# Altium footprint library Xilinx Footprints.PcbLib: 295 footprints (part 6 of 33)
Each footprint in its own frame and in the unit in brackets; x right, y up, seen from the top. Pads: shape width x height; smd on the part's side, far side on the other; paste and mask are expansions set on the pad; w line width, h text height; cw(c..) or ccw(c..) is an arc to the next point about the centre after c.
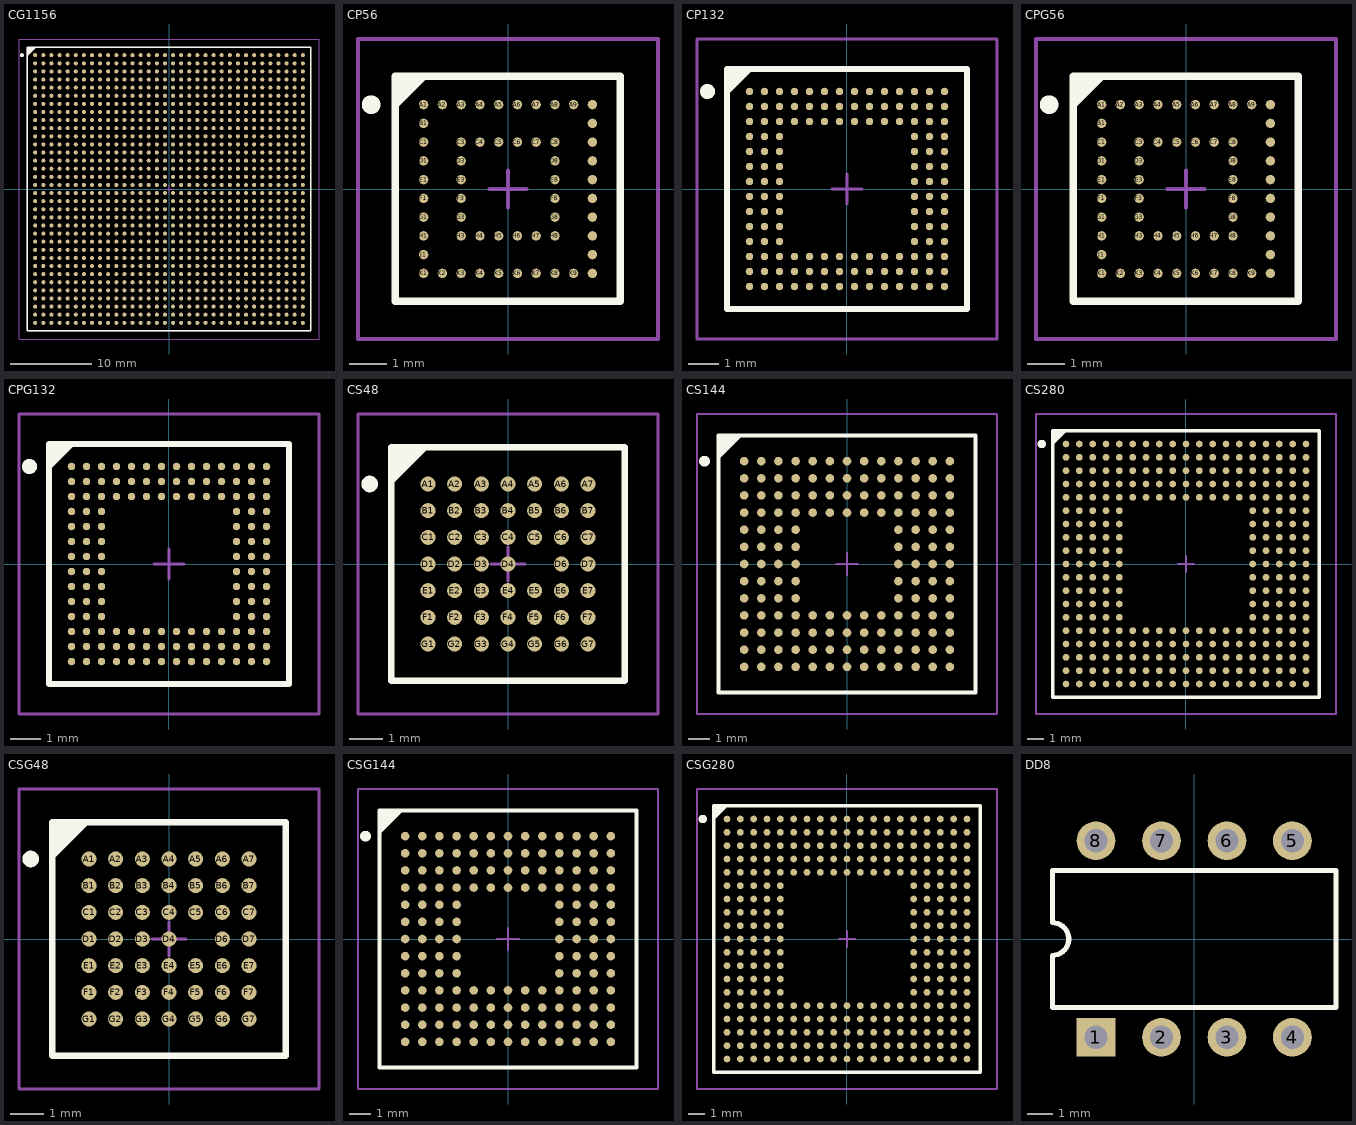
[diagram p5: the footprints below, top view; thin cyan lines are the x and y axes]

## CG1156 [mm] "1156-Ball Ceramic Ball Grid Array (CG1156)"
height 3.11
pads (1156):
  round 0.5 smd: A1(-16.5,16.5) A2(-15.5,16.5) A3(-14.5,16.5) A4(-13.5,16.5) A5(-12.5,16.5) A6(-11.5,16.5) A7(-10.5,16.5) A8(-9.5,16.5) A9(-8.5,16.5) A10(-7.5,16.5) A11(-6.5,16.5) A12(-5.5,16.5) A13(-4.5,16.5) A14(-3.5,16.5) A15(-2.5,16.5) A16(-1.5,16.5) A17(-0.5,16.5) A18(0.5,16.5) A19(1.5,16.5) A20(2.5,16.5) A21(3.5,16.5) A22(4.5,16.5) A23(5.5,16.5) A24(6.5,16.5) A25(7.5,16.5) A26(8.5,16.5) A27(9.5,16.5) A28(10.5,16.5) A29(11.5,16.5) A30(12.5,16.5) A31(13.5,16.5) A32(14.5,16.5) A33(15.5,16.5) A34(16.5,16.5) AA1(-16.5,-3.5) AA2(-15.5,-3.5) AA3(-14.5,-3.5) AA4(-13.5,-3.5) AA5(-12.5,-3.5) AA6(-11.5,-3.5) AA7(-10.5,-3.5) AA8(-9.5,-3.5) AA9(-8.5,-3.5) AA10(-7.5,-3.5) AA11(-6.5,-3.5) AA12(-5.5,-3.5) AA13(-4.5,-3.5) AA14(-3.5,-3.5) AA15(-2.5,-3.5) AA16(-1.5,-3.5) AA17(-0.5,-3.5) AA18(0.5,-3.5) AA19(1.5,-3.5) AA20(2.5,-3.5) AA21(3.5,-3.5) AA22(4.5,-3.5) AA23(5.5,-3.5) AA24(6.5,-3.5) AA25(7.5,-3.5) AA26(8.5,-3.5) AA27(9.5,-3.5) AA28(10.5,-3.5) AA29(11.5,-3.5) AA30(12.5,-3.5) AA31(13.5,-3.5) AA32(14.5,-3.5) AA33(15.5,-3.5) AA34(16.5,-3.5) AB1(-16.5,-4.5) AB2(-15.5,-4.5) AB3(-14.5,-4.5) AB4(-13.5,-4.5) AB5(-12.5,-4.5) AB6(-11.5,-4.5) AB7(-10.5,-4.5) AB8(-9.5,-4.5) AB9(-8.5,-4.5) AB10(-7.5,-4.5) AB11(-6.5,-4.5) AB12(-5.5,-4.5) AB13(-4.5,-4.5) AB14(-3.5,-4.5) AB15(-2.5,-4.5) AB16(-1.5,-4.5) AB17(-0.5,-4.5) AB18(0.5,-4.5) AB19(1.5,-4.5) AB20(2.5,-4.5) AB21(3.5,-4.5) AB22(4.5,-4.5) AB23(5.5,-4.5) AB24(6.5,-4.5) AB25(7.5,-4.5) AB26(8.5,-4.5) AB27(9.5,-4.5) AB28(10.5,-4.5) AB29(11.5,-4.5) AB30(12.5,-4.5) AB31(13.5,-4.5) AB32(14.5,-4.5) AB33(15.5,-4.5) AB34(16.5,-4.5) AC1(-16.5,-5.5) AC2(-15.5,-5.5) AC3(-14.5,-5.5) AC4(-13.5,-5.5) AC5(-12.5,-5.5) AC6(-11.5,-5.5) AC7(-10.5,-5.5) AC8(-9.5,-5.5) AC9(-8.5,-5.5) AC10(-7.5,-5.5) AC11(-6.5,-5.5) AC12(-5.5,-5.5) AC13(-4.5,-5.5) AC14(-3.5,-5.5) AC15(-2.5,-5.5) AC16(-1.5,-5.5) AC17(-0.5,-5.5) AC18(0.5,-5.5) AC19(1.5,-5.5) AC20(2.5,-5.5) AC21(3.5,-5.5) AC22(4.5,-5.5) AC23(5.5,-5.5) AC24(6.5,-5.5) AC25(7.5,-5.5) AC26(8.5,-5.5) AC27(9.5,-5.5) AC28(10.5,-5.5) AC29(11.5,-5.5) AC30(12.5,-5.5) AC31(13.5,-5.5) AC32(14.5,-5.5) AC33(15.5,-5.5) AC34(16.5,-5.5) AD1(-16.5,-6.5) AD2(-15.5,-6.5) AD3(-14.5,-6.5) AD4(-13.5,-6.5) AD5(-12.5,-6.5) AD6(-11.5,-6.5) AD7(-10.5,-6.5) AD8(-9.5,-6.5) AD9(-8.5,-6.5) AD10(-7.5,-6.5) AD11(-6.5,-6.5) AD12(-5.5,-6.5) AD13(-4.5,-6.5) AD14(-3.5,-6.5) AD15(-2.5,-6.5) AD16(-1.5,-6.5) AD17(-0.5,-6.5) AD18(0.5,-6.5) AD19(1.5,-6.5) AD20(2.5,-6.5) AD21(3.5,-6.5) AD22(4.5,-6.5) AD23(5.5,-6.5) AD24(6.5,-6.5) AD25(7.5,-6.5) AD26(8.5,-6.5) AD27(9.5,-6.5) AD28(10.5,-6.5) AD29(11.5,-6.5) AD30(12.5,-6.5) AD31(13.5,-6.5) AD32(14.5,-6.5) AD33(15.5,-6.5) AD34(16.5,-6.5) AE1(-16.5,-7.5) AE2(-15.5,-7.5) AE3(-14.5,-7.5) AE4(-13.5,-7.5) AE5(-12.5,-7.5) AE6(-11.5,-7.5) AE7(-10.5,-7.5) AE8(-9.5,-7.5) AE9(-8.5,-7.5) AE10(-7.5,-7.5) AE11(-6.5,-7.5) AE12(-5.5,-7.5) AE13(-4.5,-7.5) AE14(-3.5,-7.5) AE15(-2.5,-7.5) AE16(-1.5,-7.5) AE17(-0.5,-7.5) AE18(0.5,-7.5) AE19(1.5,-7.5) AE20(2.5,-7.5) AE21(3.5,-7.5) AE22(4.5,-7.5) AE23(5.5,-7.5) AE24(6.5,-7.5) AE25(7.5,-7.5) AE26(8.5,-7.5) AE27(9.5,-7.5) AE28(10.5,-7.5) AE29(11.5,-7.5) AE30(12.5,-7.5) AE31(13.5,-7.5) AE32(14.5,-7.5) AE33(15.5,-7.5) AE34(16.5,-7.5) AF1(-16.5,-8.5) AF2(-15.5,-8.5) AF3(-14.5,-8.5) AF4(-13.5,-8.5) AF5(-12.5,-8.5) AF6(-11.5,-8.5) AF7(-10.5,-8.5) AF8(-9.5,-8.5) AF9(-8.5,-8.5) AF10(-7.5,-8.5) AF11(-6.5,-8.5) AF12(-5.5,-8.5) AF13(-4.5,-8.5) AF14(-3.5,-8.5) AF15(-2.5,-8.5) AF16(-1.5,-8.5) AF17(-0.5,-8.5) AF18(0.5,-8.5) AF19(1.5,-8.5) AF20(2.5,-8.5) AF21(3.5,-8.5) AF22(4.5,-8.5) AF23(5.5,-8.5) AF24(6.5,-8.5) AF25(7.5,-8.5) AF26(8.5,-8.5) AF27(9.5,-8.5) AF28(10.5,-8.5) AF29(11.5,-8.5) AF30(12.5,-8.5) AF31(13.5,-8.5) AF32(14.5,-8.5) AF33(15.5,-8.5) AF34(16.5,-8.5) AG1(-16.5,-9.5) AG2(-15.5,-9.5) AG3(-14.5,-9.5) AG4(-13.5,-9.5) AG5(-12.5,-9.5) AG6(-11.5,-9.5) AG7(-10.5,-9.5) AG8(-9.5,-9.5) AG9(-8.5,-9.5) AG10(-7.5,-9.5) AG11(-6.5,-9.5) AG12(-5.5,-9.5) AG13(-4.5,-9.5) AG14(-3.5,-9.5) AG15(-2.5,-9.5) AG16(-1.5,-9.5) AG17(-0.5,-9.5) AG18(0.5,-9.5) AG19(1.5,-9.5) AG20(2.5,-9.5) AG21(3.5,-9.5) AG22(4.5,-9.5) AG23(5.5,-9.5) AG24(6.5,-9.5) AG25(7.5,-9.5) AG26(8.5,-9.5) AG27(9.5,-9.5) AG28(10.5,-9.5) AG29(11.5,-9.5) AG30(12.5,-9.5) AG31(13.5,-9.5) AG32(14.5,-9.5) AG33(15.5,-9.5) AG34(16.5,-9.5) AH1(-16.5,-10.5) AH2(-15.5,-10.5) AH3(-14.5,-10.5) AH4(-13.5,-10.5) AH5(-12.5,-10.5) AH6(-11.5,-10.5) AH7(-10.5,-10.5) AH8(-9.5,-10.5) AH9(-8.5,-10.5) AH10(-7.5,-10.5) AH11(-6.5,-10.5) AH12(-5.5,-10.5) AH13(-4.5,-10.5) AH14(-3.5,-10.5) AH15(-2.5,-10.5) AH16(-1.5,-10.5) AH17(-0.5,-10.5) AH18(0.5,-10.5) AH19(1.5,-10.5) AH20(2.5,-10.5) AH21(3.5,-10.5) AH22(4.5,-10.5) AH23(5.5,-10.5) AH24(6.5,-10.5) AH25(7.5,-10.5) AH26(8.5,-10.5) AH27(9.5,-10.5) AH28(10.5,-10.5) AH29(11.5,-10.5) AH30(12.5,-10.5) AH31(13.5,-10.5) AH32(14.5,-10.5) AH33(15.5,-10.5) AH34(16.5,-10.5) AJ1(-16.5,-11.5) AJ2(-15.5,-11.5) AJ3(-14.5,-11.5) AJ4(-13.5,-11.5) AJ5(-12.5,-11.5) AJ6(-11.5,-11.5) AJ7(-10.5,-11.5) AJ8(-9.5,-11.5) AJ9(-8.5,-11.5) AJ10(-7.5,-11.5) AJ11(-6.5,-11.5) AJ12(-5.5,-11.5) AJ13(-4.5,-11.5) AJ14(-3.5,-11.5) AJ15(-2.5,-11.5) AJ16(-1.5,-11.5) AJ17(-0.5,-11.5) AJ18(0.5,-11.5) AJ19(1.5,-11.5) AJ20(2.5,-11.5) AJ21(3.5,-11.5) AJ22(4.5,-11.5) AJ23(5.5,-11.5) AJ24(6.5,-11.5) AJ25(7.5,-11.5) AJ26(8.5,-11.5) AJ27(9.5,-11.5) AJ28(10.5,-11.5) AJ29(11.5,-11.5) AJ30(12.5,-11.5) AJ31(13.5,-11.5) AJ32(14.5,-11.5) AJ33(15.5,-11.5) AJ34(16.5,-11.5) AK1(-16.5,-12.5) AK2(-15.5,-12.5) AK3(-14.5,-12.5) AK4(-13.5,-12.5) AK5(-12.5,-12.5) AK6(-11.5,-12.5) AK7(-10.5,-12.5) AK8(-9.5,-12.5) AK9(-8.5,-12.5) AK10(-7.5,-12.5) AK11(-6.5,-12.5) AK12(-5.5,-12.5) AK13(-4.5,-12.5) AK14(-3.5,-12.5) AK15(-2.5,-12.5) AK16(-1.5,-12.5) AK17(-0.5,-12.5) AK18(0.5,-12.5) AK19(1.5,-12.5) AK20(2.5,-12.5) AK21(3.5,-12.5) AK22(4.5,-12.5) AK23(5.5,-12.5) AK24(6.5,-12.5) AK25(7.5,-12.5) AK26(8.5,-12.5) AK27(9.5,-12.5) AK28(10.5,-12.5) AK29(11.5,-12.5) AK30(12.5,-12.5) AK31(13.5,-12.5) AK32(14.5,-12.5) AK33(15.5,-12.5) AK34(16.5,-12.5) AL1(-16.5,-13.5) AL2(-15.5,-13.5) AL3(-14.5,-13.5) AL4(-13.5,-13.5) AL5(-12.5,-13.5) AL6(-11.5,-13.5) AL7(-10.5,-13.5) AL8(-9.5,-13.5) AL9(-8.5,-13.5) AL10(-7.5,-13.5) AL11(-6.5,-13.5) AL12(-5.5,-13.5) AL13(-4.5,-13.5) AL14(-3.5,-13.5) AL15(-2.5,-13.5) AL16(-1.5,-13.5) AL17(-0.5,-13.5) AL18(0.5,-13.5) AL19(1.5,-13.5) AL20(2.5,-13.5) AL21(3.5,-13.5) AL22(4.5,-13.5) AL23(5.5,-13.5) AL24(6.5,-13.5) AL25(7.5,-13.5) AL26(8.5,-13.5) AL27(9.5,-13.5) AL28(10.5,-13.5) AL29(11.5,-13.5) AL30(12.5,-13.5) AL31(13.5,-13.5) AL32(14.5,-13.5) AL33(15.5,-13.5) AL34(16.5,-13.5) AM1(-16.5,-14.5) AM2(-15.5,-14.5) AM3(-14.5,-14.5) AM4(-13.5,-14.5) AM5(-12.5,-14.5) AM6(-11.5,-14.5) AM7(-10.5,-14.5) AM8(-9.5,-14.5) AM9(-8.5,-14.5) AM10(-7.5,-14.5) AM11(-6.5,-14.5) AM12(-5.5,-14.5) AM13(-4.5,-14.5) AM14(-3.5,-14.5) AM15(-2.5,-14.5) AM16(-1.5,-14.5) AM17(-0.5,-14.5) AM18(0.5,-14.5) AM19(1.5,-14.5) AM20(2.5,-14.5) AM21(3.5,-14.5) AM22(4.5,-14.5) AM23(5.5,-14.5) AM24(6.5,-14.5) AM25(7.5,-14.5) AM26(8.5,-14.5) AM27(9.5,-14.5) AM28(10.5,-14.5) AM29(11.5,-14.5) AM30(12.5,-14.5) AM31(13.5,-14.5) AM32(14.5,-14.5) AM33(15.5,-14.5) AM34(16.5,-14.5) AN1(-16.5,-15.5) AN2(-15.5,-15.5) AN3(-14.5,-15.5) AN4(-13.5,-15.5) AN5(-12.5,-15.5) AN6(-11.5,-15.5) AN7(-10.5,-15.5) AN8(-9.5,-15.5) AN9(-8.5,-15.5) AN10(-7.5,-15.5) AN11(-6.5,-15.5) AN12(-5.5,-15.5) AN13(-4.5,-15.5) AN14(-3.5,-15.5) AN15(-2.5,-15.5) AN16(-1.5,-15.5) AN17(-0.5,-15.5) AN18(0.5,-15.5) AN19(1.5,-15.5) AN20(2.5,-15.5) AN21(3.5,-15.5) AN22(4.5,-15.5) AN23(5.5,-15.5) AN24(6.5,-15.5) AN25(7.5,-15.5) AN26(8.5,-15.5) AN27(9.5,-15.5) AN28(10.5,-15.5) AN29(11.5,-15.5) AN30(12.5,-15.5) AN31(13.5,-15.5) AN32(14.5,-15.5) AN33(15.5,-15.5) AN34(16.5,-15.5) AP1(-16.5,-16.5) AP2(-15.5,-16.5) AP3(-14.5,-16.5) AP4(-13.5,-16.5) AP5(-12.5,-16.5) AP6(-11.5,-16.5) AP7(-10.5,-16.5) AP8(-9.5,-16.5) AP9(-8.5,-16.5) AP10(-7.5,-16.5) AP11(-6.5,-16.5) AP12(-5.5,-16.5) AP13(-4.5,-16.5) AP14(-3.5,-16.5) AP15(-2.5,-16.5) AP16(-1.5,-16.5) AP17(-0.5,-16.5) AP18(0.5,-16.5) AP19(1.5,-16.5) AP20(2.5,-16.5) AP21(3.5,-16.5) AP22(4.5,-16.5) AP23(5.5,-16.5) AP24(6.5,-16.5) AP25(7.5,-16.5) AP26(8.5,-16.5) AP27(9.5,-16.5) AP28(10.5,-16.5) AP29(11.5,-16.5) AP30(12.5,-16.5) AP31(13.5,-16.5) AP32(14.5,-16.5) AP33(15.5,-16.5) AP34(16.5,-16.5) B1(-16.5,15.5) B2(-15.5,15.5) B3(-14.5,15.5) B4(-13.5,15.5) B5(-12.5,15.5) B6(-11.5,15.5) B7(-10.5,15.5) B8(-9.5,15.5) B9(-8.5,15.5) B10(-7.5,15.5) B11(-6.5,15.5) B12(-5.5,15.5) B13(-4.5,15.5) B14(-3.5,15.5) B15(-2.5,15.5) B16(-1.5,15.5) B17(-0.5,15.5) B18(0.5,15.5) B19(1.5,15.5) B20(2.5,15.5) B21(3.5,15.5) B22(4.5,15.5) B23(5.5,15.5) B24(6.5,15.5) B25(7.5,15.5) B26(8.5,15.5) B27(9.5,15.5) B28(10.5,15.5) B29(11.5,15.5) B30(12.5,15.5) B31(13.5,15.5) B32(14.5,15.5) B33(15.5,15.5) B34(16.5,15.5) C1(-16.5,14.5) C2(-15.5,14.5) C3(-14.5,14.5) C4(-13.5,14.5) C5(-12.5,14.5) C6(-11.5,14.5) C7(-10.5,14.5) C8(-9.5,14.5) C9(-8.5,14.5) C10(-7.5,14.5) C11(-6.5,14.5) C12(-5.5,14.5) C13(-4.5,14.5) C14(-3.5,14.5) C15(-2.5,14.5) C16(-1.5,14.5) C17(-0.5,14.5) C18(0.5,14.5) C19(1.5,14.5) C20(2.5,14.5) C21(3.5,14.5) C22(4.5,14.5) C23(5.5,14.5) C24(6.5,14.5) C25(7.5,14.5) C26(8.5,14.5) C27(9.5,14.5) C28(10.5,14.5) C29(11.5,14.5) C30(12.5,14.5) C31(13.5,14.5) C32(14.5,14.5) C33(15.5,14.5) C34(16.5,14.5) D1(-16.5,13.5) D2(-15.5,13.5) D3(-14.5,13.5) D4(-13.5,13.5) D5(-12.5,13.5) D6(-11.5,13.5) D7(-10.5,13.5) D8(-9.5,13.5) D9(-8.5,13.5) D10(-7.5,13.5) D11(-6.5,13.5) D12(-5.5,13.5) D13(-4.5,13.5) D14(-3.5,13.5) D15(-2.5,13.5) D16(-1.5,13.5) D17(-0.5,13.5) D18(0.5,13.5) D19(1.5,13.5) D20(2.5,13.5) D21(3.5,13.5) D22(4.5,13.5) D23(5.5,13.5) D24(6.5,13.5) D25(7.5,13.5) D26(8.5,13.5) D27(9.5,13.5) D28(10.5,13.5) D29(11.5,13.5) D30(12.5,13.5) D31(13.5,13.5) D32(14.5,13.5) D33(15.5,13.5) D34(16.5,13.5) E1(-16.5,12.5) E2(-15.5,12.5) E3(-14.5,12.5) E4(-13.5,12.5) E5(-12.5,12.5) E6(-11.5,12.5) E7(-10.5,12.5) E8(-9.5,12.5) E9(-8.5,12.5) E10(-7.5,12.5) E11(-6.5,12.5) E12(-5.5,12.5) E13(-4.5,12.5) E14(-3.5,12.5) E15(-2.5,12.5) E16(-1.5,12.5) E17(-0.5,12.5) E18(0.5,12.5) E19(1.5,12.5) E20(2.5,12.5) E21(3.5,12.5) E22(4.5,12.5) E23(5.5,12.5) E24(6.5,12.5) E25(7.5,12.5) E26(8.5,12.5) E27(9.5,12.5) E28(10.5,12.5) E29(11.5,12.5) E30(12.5,12.5) E31(13.5,12.5) E32(14.5,12.5) E33(15.5,12.5) E34(16.5,12.5) F1(-16.5,11.5) F2(-15.5,11.5) F3(-14.5,11.5) F4(-13.5,11.5) F5(-12.5,11.5) F6(-11.5,11.5) F7(-10.5,11.5) F8(-9.5,11.5) F9(-8.5,11.5) F10(-7.5,11.5) F11(-6.5,11.5) F12(-5.5,11.5) F13(-4.5,11.5) F14(-3.5,11.5) F15(-2.5,11.5) F16(-1.5,11.5) F17(-0.5,11.5) F18(0.5,11.5) F19(1.5,11.5) F20(2.5,11.5) F21(3.5,11.5) F22(4.5,11.5) F23(5.5,11.5) F24(6.5,11.5) F25(7.5,11.5) F26(8.5,11.5) F27(9.5,11.5) F28(10.5,11.5) F29(11.5,11.5) F30(12.5,11.5) F31(13.5,11.5) F32(14.5,11.5) F33(15.5,11.5) F34(16.5,11.5) G1(-16.5,10.5) G2(-15.5,10.5) G3(-14.5,10.5) G4(-13.5,10.5) G5(-12.5,10.5) G6(-11.5,10.5) G7(-10.5,10.5) G8(-9.5,10.5) G9(-8.5,10.5) G10(-7.5,10.5) G11(-6.5,10.5) G12(-5.5,10.5) G13(-4.5,10.5) G14(-3.5,10.5) G15(-2.5,10.5) G16(-1.5,10.5) G17(-0.5,10.5) G18(0.5,10.5) G19(1.5,10.5) G20(2.5,10.5) G21(3.5,10.5) G22(4.5,10.5) G23(5.5,10.5) G24(6.5,10.5) G25(7.5,10.5) G26(8.5,10.5) G27(9.5,10.5) G28(10.5,10.5) G29(11.5,10.5) G30(12.5,10.5) G31(13.5,10.5) G32(14.5,10.5) G33(15.5,10.5) G34(16.5,10.5) H1(-16.5,9.5) H2(-15.5,9.5) H3(-14.5,9.5) H4(-13.5,9.5) H5(-12.5,9.5) H6(-11.5,9.5) H7(-10.5,9.5) H8(-9.5,9.5) H9(-8.5,9.5) H10(-7.5,9.5) H11(-6.5,9.5) H12(-5.5,9.5) H13(-4.5,9.5) H14(-3.5,9.5) H15(-2.5,9.5) H16(-1.5,9.5) H17(-0.5,9.5) H18(0.5,9.5) H19(1.5,9.5) H20(2.5,9.5) H21(3.5,9.5) H22(4.5,9.5) H23(5.5,9.5) H24(6.5,9.5) H25(7.5,9.5) H26(8.5,9.5) H27(9.5,9.5) H28(10.5,9.5) H29(11.5,9.5) H30(12.5,9.5) H31(13.5,9.5) H32(14.5,9.5) H33(15.5,9.5) H34(16.5,9.5) J1(-16.5,8.5) J2(-15.5,8.5) J3(-14.5,8.5) J4(-13.5,8.5) J5(-12.5,8.5) J6(-11.5,8.5) J7(-10.5,8.5) J8(-9.5,8.5) J9(-8.5,8.5) J10(-7.5,8.5) J11(-6.5,8.5) J12(-5.5,8.5) J13(-4.5,8.5) J14(-3.5,8.5) J15(-2.5,8.5) J16(-1.5,8.5) J17(-0.5,8.5) J18(0.5,8.5) J19(1.5,8.5) J20(2.5,8.5) J21(3.5,8.5) J22(4.5,8.5) J23(5.5,8.5) J24(6.5,8.5) J25(7.5,8.5) J26(8.5,8.5) J27(9.5,8.5) J28(10.5,8.5) J29(11.5,8.5) J30(12.5,8.5) J31(13.5,8.5) J32(14.5,8.5) J33(15.5,8.5) J34(16.5,8.5) K1(-16.5,7.5) K2(-15.5,7.5) K3(-14.5,7.5) K4(-13.5,7.5) K5(-12.5,7.5) K6(-11.5,7.5) K7(-10.5,7.5) K8(-9.5,7.5) K9(-8.5,7.5) K10(-7.5,7.5) K11(-6.5,7.5) K12(-5.5,7.5) K13(-4.5,7.5) K14(-3.5,7.5) K15(-2.5,7.5) K16(-1.5,7.5) K17(-0.5,7.5) K18(0.5,7.5) K19(1.5,7.5) K20(2.5,7.5) K21(3.5,7.5) K22(4.5,7.5) K23(5.5,7.5) K24(6.5,7.5) K25(7.5,7.5) K26(8.5,7.5) K27(9.5,7.5) K28(10.5,7.5) K29(11.5,7.5) K30(12.5,7.5) K31(13.5,7.5) K32(14.5,7.5) K33(15.5,7.5) K34(16.5,7.5) L1(-16.5,6.5) L2(-15.5,6.5) L3(-14.5,6.5) L4(-13.5,6.5) L5(-12.5,6.5) L6(-11.5,6.5) L7(-10.5,6.5) L8(-9.5,6.5) L9(-8.5,6.5) L10(-7.5,6.5) L11(-6.5,6.5) L12(-5.5,6.5) L13(-4.5,6.5) L14(-3.5,6.5) L15(-2.5,6.5) L16(-1.5,6.5) L17(-0.5,6.5) L18(0.5,6.5) L19(1.5,6.5) L20(2.5,6.5) L21(3.5,6.5) L22(4.5,6.5) L23(5.5,6.5) L24(6.5,6.5) L25(7.5,6.5) L26(8.5,6.5) L27(9.5,6.5) L28(10.5,6.5) L29(11.5,6.5) L30(12.5,6.5) L31(13.5,6.5) L32(14.5,6.5) L33(15.5,6.5) L34(16.5,6.5) M1(-16.5,5.5) M2(-15.5,5.5) M3(-14.5,5.5) M4(-13.5,5.5) M5(-12.5,5.5) M6(-11.5,5.5) M7(-10.5,5.5) M8(-9.5,5.5) M9(-8.5,5.5) M10(-7.5,5.5) M11(-6.5,5.5) M12(-5.5,5.5) M13(-4.5,5.5) M14(-3.5,5.5) M15(-2.5,5.5) M16(-1.5,5.5) M17(-0.5,5.5) M18(0.5,5.5) M19(1.5,5.5) M20(2.5,5.5) M21(3.5,5.5) M22(4.5,5.5) M23(5.5,5.5) M24(6.5,5.5) M25(7.5,5.5) M26(8.5,5.5) M27(9.5,5.5) M28(10.5,5.5) M29(11.5,5.5) M30(12.5,5.5) M31(13.5,5.5) M32(14.5,5.5) M33(15.5,5.5) M34(16.5,5.5) N1(-16.5,4.5) N2(-15.5,4.5) N3(-14.5,4.5) N4(-13.5,4.5) N5(-12.5,4.5) N6(-11.5,4.5) N7(-10.5,4.5) N8(-9.5,4.5) N9(-8.5,4.5) N10(-7.5,4.5) N11(-6.5,4.5) N12(-5.5,4.5) N13(-4.5,4.5) N14(-3.5,4.5) N15(-2.5,4.5) N16(-1.5,4.5) N17(-0.5,4.5) N18(0.5,4.5) N19(1.5,4.5) N20(2.5,4.5) N21(3.5,4.5) N22(4.5,4.5) N23(5.5,4.5) N24(6.5,4.5) N25(7.5,4.5) N26(8.5,4.5) N27(9.5,4.5) N28(10.5,4.5) N29(11.5,4.5) N30(12.5,4.5) N31(13.5,4.5) N32(14.5,4.5) N33(15.5,4.5) N34(16.5,4.5) P1(-16.5,3.5) P2(-15.5,3.5) P3(-14.5,3.5) P4(-13.5,3.5) P5(-12.5,3.5) P6(-11.5,3.5) P7(-10.5,3.5) P8(-9.5,3.5) P9(-8.5,3.5) P10(-7.5,3.5) P11(-6.5,3.5) P12(-5.5,3.5) P13(-4.5,3.5) P14(-3.5,3.5) P15(-2.5,3.5) P16(-1.5,3.5) P17(-0.5,3.5) P18(0.5,3.5) P19(1.5,3.5) P20(2.5,3.5) P21(3.5,3.5) P22(4.5,3.5) P23(5.5,3.5) P24(6.5,3.5) P25(7.5,3.5) P26(8.5,3.5) P27(9.5,3.5) P28(10.5,3.5) P29(11.5,3.5) P30(12.5,3.5) P31(13.5,3.5) P32(14.5,3.5) P33(15.5,3.5) P34(16.5,3.5) R1(-16.5,2.5) R2(-15.5,2.5) R3(-14.5,2.5) R4(-13.5,2.5) R5(-12.5,2.5) R6(-11.5,2.5) R7(-10.5,2.5) R8(-9.5,2.5) R9(-8.5,2.5) R10(-7.5,2.5) R11(-6.5,2.5) R12(-5.5,2.5) R13(-4.5,2.5) R14(-3.5,2.5) R15(-2.5,2.5) R16(-1.5,2.5) R17(-0.5,2.5) R18(0.5,2.5) R19(1.5,2.5) R20(2.5,2.5) R21(3.5,2.5) R22(4.5,2.5) R23(5.5,2.5) R24(6.5,2.5) R25(7.5,2.5) R26(8.5,2.5) R27(9.5,2.5) R28(10.5,2.5) R29(11.5,2.5) R30(12.5,2.5) R31(13.5,2.5) R32(14.5,2.5) R33(15.5,2.5) R34(16.5,2.5) T1(-16.5,1.5) T2(-15.5,1.5) T3(-14.5,1.5) T4(-13.5,1.5) T5(-12.5,1.5) T6(-11.5,1.5) T7(-10.5,1.5) T8(-9.5,1.5) T9(-8.5,1.5) T10(-7.5,1.5) T11(-6.5,1.5) T12(-5.5,1.5) T13(-4.5,1.5) T14(-3.5,1.5) T15(-2.5,1.5) T16(-1.5,1.5) T17(-0.5,1.5) T18(0.5,1.5) T19(1.5,1.5) T20(2.5,1.5) T21(3.5,1.5) T22(4.5,1.5) T23(5.5,1.5) T24(6.5,1.5) T25(7.5,1.5) T26(8.5,1.5) T27(9.5,1.5) T28(10.5,1.5) T29(11.5,1.5) T30(12.5,1.5) T31(13.5,1.5) T32(14.5,1.5) T33(15.5,1.5) T34(16.5,1.5) U1(-16.5,0.5) U2(-15.5,0.5) U3(-14.5,0.5) U4(-13.5,0.5) U5(-12.5,0.5) U6(-11.5,0.5) U7(-10.5,0.5) U8(-9.5,0.5) U9(-8.5,0.5) U10(-7.5,0.5) U11(-6.5,0.5) U12(-5.5,0.5) U13(-4.5,0.5) U14(-3.5,0.5) U15(-2.5,0.5) U16(-1.5,0.5) U17(-0.5,0.5) U18(0.5,0.5) U19(1.5,0.5) U20(2.5,0.5) U21(3.5,0.5) U22(4.5,0.5) U23(5.5,0.5) U24(6.5,0.5) U25(7.5,0.5) U26(8.5,0.5) U27(9.5,0.5) U28(10.5,0.5) U29(11.5,0.5) U30(12.5,0.5) U31(13.5,0.5) U32(14.5,0.5) U33(15.5,0.5) U34(16.5,0.5) V1(-16.5,-0.5) V2(-15.5,-0.5) V3(-14.5,-0.5) V4(-13.5,-0.5) V5(-12.5,-0.5) V6(-11.5,-0.5) V7(-10.5,-0.5) V8(-9.5,-0.5) V9(-8.5,-0.5) V10(-7.5,-0.5) V11(-6.5,-0.5) V12(-5.5,-0.5) V13(-4.5,-0.5) V14(-3.5,-0.5) V15(-2.5,-0.5) V16(-1.5,-0.5) V17(-0.5,-0.5) V18(0.5,-0.5) V19(1.5,-0.5) V20(2.5,-0.5) V21(3.5,-0.5) V22(4.5,-0.5) V23(5.5,-0.5) V24(6.5,-0.5) V25(7.5,-0.5) V26(8.5,-0.5) V27(9.5,-0.5) V28(10.5,-0.5) V29(11.5,-0.5) V30(12.5,-0.5) V31(13.5,-0.5) V32(14.5,-0.5) V33(15.5,-0.5) V34(16.5,-0.5) W1(-16.5,-1.5) W2(-15.5,-1.5) W3(-14.5,-1.5) W4(-13.5,-1.5) W5(-12.5,-1.5) W6(-11.5,-1.5) W7(-10.5,-1.5) W8(-9.5,-1.5) W9(-8.5,-1.5) W10(-7.5,-1.5) W11(-6.5,-1.5) W12(-5.5,-1.5) W13(-4.5,-1.5) W14(-3.5,-1.5) W15(-2.5,-1.5) W16(-1.5,-1.5) W17(-0.5,-1.5) W18(0.5,-1.5) W19(1.5,-1.5) W20(2.5,-1.5) W21(3.5,-1.5) W22(4.5,-1.5) W23(5.5,-1.5) W24(6.5,-1.5) W25(7.5,-1.5) W26(8.5,-1.5) W27(9.5,-1.5) W28(10.5,-1.5) W29(11.5,-1.5) W30(12.5,-1.5) W31(13.5,-1.5) W32(14.5,-1.5) W33(15.5,-1.5) W34(16.5,-1.5) Y1(-16.5,-2.5) Y2(-15.5,-2.5) Y3(-14.5,-2.5) Y4(-13.5,-2.5) Y5(-12.5,-2.5) Y6(-11.5,-2.5) Y7(-10.5,-2.5) Y8(-9.5,-2.5) Y9(-8.5,-2.5) Y10(-7.5,-2.5) Y11(-6.5,-2.5) Y12(-5.5,-2.5) Y13(-4.5,-2.5) Y14(-3.5,-2.5) Y15(-2.5,-2.5) Y16(-1.5,-2.5) Y17(-0.5,-2.5) Y18(0.5,-2.5) Y19(1.5,-2.5) Y20(2.5,-2.5) Y21(3.5,-2.5) Y22(4.5,-2.5) Y23(5.5,-2.5) Y24(6.5,-2.5) Y25(7.5,-2.5) Y26(8.5,-2.5) Y27(9.5,-2.5) Y28(10.5,-2.5) Y29(11.5,-2.5) Y30(12.5,-2.5) Y31(13.5,-2.5) Y32(14.5,-2.5) Y33(15.5,-2.5) Y34(16.5,-2.5)
Top Overlay:
  circle w0.25: c-18.15,16.5 r0.125
  region: -16.5,17.5 -17.5,16.5 -17.5,17.5
  lines w0.2: -17.5,16.5 -16.5,17.5 ; -17.5,-17.5 17.5,-17.5 17.5,17.5 -17.5,17.5 -17.5,-17.5
Mechanical 13:
  lines w0.1: -17.5,-17.5 17.5,-17.5 17.5,17.5 -17.5,17.5 -17.5,-17.5
Mechanical 15:
  lines w0.1: -0.5,0 0.5,0 ; 0,-0.5 0,0.5 ; -18.5,-18.5 18.5,-18.5 18.5,18.5 -18.5,18.5 -18.5,-18.5
3D body: height 3.11, standoff 0, extent -17.5,-17.5 17.5,17.5

## CP56 [mm] "56-Ball Chip Scale Ball Grid Array 0.5 mm Pitch (CP56)"
height 1.35
pads (56):
  round 0.25 smd: A1(-2.25,2.25) A2(-1.75,2.25) A3(-1.25,2.25) A4(-0.75,2.25) A5(-0.25,2.25) A6(0.25,2.25) A7(0.75,2.25) A8(1.25,2.25) A9(1.75,2.25) A10(2.25,2.25) B1(-2.25,1.75) B10(2.25,1.75) C1(-2.25,1.25) C3(-1.25,1.25) C4(-0.75,1.25) C5(-0.25,1.25) C6(0.25,1.25) C7(0.75,1.25) C8(1.25,1.25) C10(2.25,1.25) D1(-2.25,0.75) D3(-1.25,0.75) D8(1.25,0.75) D10(2.25,0.75) E1(-2.25,0.25) E3(-1.25,0.25) E8(1.25,0.25) E10(2.25,0.25) F1(-2.25,-0.25) F3(-1.25,-0.25) F8(1.25,-0.25) F10(2.25,-0.25) G1(-2.25,-0.75) G3(-1.25,-0.75) G8(1.25,-0.75) G10(2.25,-0.75) H1(-2.25,-1.25) H3(-1.25,-1.25) H4(-0.75,-1.25) H5(-0.25,-1.25) H6(0.25,-1.25) H7(0.75,-1.25) H8(1.25,-1.25) H10(2.25,-1.25) J1(-2.25,-1.75) J10(2.25,-1.75) K1(-2.25,-2.25) K2(-1.75,-2.25) K3(-1.25,-2.25) K4(-0.75,-2.25) K5(-0.25,-2.25) K6(0.25,-2.25) K7(0.75,-2.25) K8(1.25,-2.25) K9(1.75,-2.25) K10(2.25,-2.25)
Top Overlay:
  circle w0.25: c-3.65,2.25 r0.125
  region: -2.242,3 -3,2.242 -3,3
  lines w0.2: -3,2.242 -2.242,3 ; -3,-3 3,-3 3,3 -3,3 -3,-3
Mechanical 13:
  lines w0.1: -3,-3 3,-3 3,3 -3,3 -3,-3
Mechanical 15:
  lines w0.1: -0.5,0 0.5,0 ; 0,-0.5 0,0.5 ; -4,-4 4,-4 4,4 -4,4 -4,-4
3D body: height 1.35, standoff 0, extent -3,-3 3,3

## CP132 [mm] "132-Ball Chip Scale Ball Grid Array 0.5 mm Pitch (CP132)"
height 1.1
pads (132):
  round 0.25 smd: A1(-3.25,3.25) A2(-2.75,3.25) A3(-2.25,3.25) A4(-1.75,3.25) A5(-1.25,3.25) A6(-0.75,3.25) A7(-0.25,3.25) A8(0.25,3.25) A9(0.75,3.25) A10(1.25,3.25) A11(1.75,3.25) A12(2.25,3.25) A13(2.75,3.25) A14(3.25,3.25) B1(-3.25,2.75) B2(-2.75,2.75) B3(-2.25,2.75) B4(-1.75,2.75) B5(-1.25,2.75) B6(-0.75,2.75) B7(-0.25,2.75) B8(0.25,2.75) B9(0.75,2.75) B10(1.25,2.75) B11(1.75,2.75) B12(2.25,2.75) B13(2.75,2.75) B14(3.25,2.75) C1(-3.25,2.25) C2(-2.75,2.25) C3(-2.25,2.25) C4(-1.75,2.25) C5(-1.25,2.25) C6(-0.75,2.25) C7(-0.25,2.25) C8(0.25,2.25) C9(0.75,2.25) C10(1.25,2.25) C11(1.75,2.25) C12(2.25,2.25) C13(2.75,2.25) C14(3.25,2.25) D1(-3.25,1.75) D2(-2.75,1.75) D3(-2.25,1.75) D12(2.25,1.75) D13(2.75,1.75) D14(3.25,1.75) E1(-3.25,1.25) E2(-2.75,1.25) E3(-2.25,1.25) E12(2.25,1.25) E13(2.75,1.25) E14(3.25,1.25) F1(-3.25,0.75) F2(-2.75,0.75) F3(-2.25,0.75) F12(2.25,0.75) F13(2.75,0.75) F14(3.25,0.75) G1(-3.25,0.25) G2(-2.75,0.25) G3(-2.25,0.25) G12(2.25,0.25) G13(2.75,0.25) G14(3.25,0.25) H1(-3.25,-0.25) H2(-2.75,-0.25) H3(-2.25,-0.25) H12(2.25,-0.25) H13(2.75,-0.25) H14(3.25,-0.25) J1(-3.25,-0.75) J2(-2.75,-0.75) J3(-2.25,-0.75) J12(2.25,-0.75) J13(2.75,-0.75) J14(3.25,-0.75) K1(-3.25,-1.25) K2(-2.75,-1.25) K3(-2.25,-1.25) K12(2.25,-1.25) K13(2.75,-1.25) K14(3.25,-1.25) L1(-3.25,-1.75) L2(-2.75,-1.75) L3(-2.25,-1.75) L12(2.25,-1.75) L13(2.75,-1.75) L14(3.25,-1.75) M1(-3.25,-2.25) M2(-2.75,-2.25) M3(-2.25,-2.25) M4(-1.75,-2.25) M5(-1.25,-2.25) M6(-0.75,-2.25) M7(-0.25,-2.25) M8(0.25,-2.25) M9(0.75,-2.25) M10(1.25,-2.25) M11(1.75,-2.25) M12(2.25,-2.25) M13(2.75,-2.25) M14(3.25,-2.25) N1(-3.25,-2.75) N2(-2.75,-2.75) N3(-2.25,-2.75) N4(-1.75,-2.75) N5(-1.25,-2.75) N6(-0.75,-2.75) N7(-0.25,-2.75) N8(0.25,-2.75) N9(0.75,-2.75) N10(1.25,-2.75) N11(1.75,-2.75) N12(2.25,-2.75) N13(2.75,-2.75) N14(3.25,-2.75) P1(-3.25,-3.25) P2(-2.75,-3.25) P3(-2.25,-3.25) P4(-1.75,-3.25) P5(-1.25,-3.25) P6(-0.75,-3.25) P7(-0.25,-3.25) P8(0.25,-3.25) P9(0.75,-3.25) P10(1.25,-3.25) P11(1.75,-3.25) P12(2.25,-3.25) P13(2.75,-3.25) P14(3.25,-3.25)
Top Overlay:
  circle w0.25: c-4.65,3.25 r0.125
  region: -3.242,4 -4,3.242 -4,4
  lines w0.2: -4,3.242 -3.242,4 ; -4,-4 4,-4 4,4 -4,4 -4,-4
Mechanical 13:
  lines w0.1: -4,-4 4,-4 4,4 -4,4 -4,-4
Mechanical 15:
  lines w0.1: -0.5,0 0.5,0 ; 0,-0.5 0,0.5 ; -5,-5 5,-5 5,5 -5,5 -5,-5
3D body: height 1.1, standoff 0, extent -4,-4 4,4

## CPG56 [mm] "56-Ball Chip Scale Ball Grid Array 0.5 mm Pitch (CPG56) - Pb-Free"
height 1.35
pads (56):
  round 0.25 smd: A1(-2.25,2.25) A2(-1.75,2.25) A3(-1.25,2.25) A4(-0.75,2.25) A5(-0.25,2.25) A6(0.25,2.25) A7(0.75,2.25) A8(1.25,2.25) A9(1.75,2.25) A10(2.25,2.25) B1(-2.25,1.75) B10(2.25,1.75) C1(-2.25,1.25) C3(-1.25,1.25) C4(-0.75,1.25) C5(-0.25,1.25) C6(0.25,1.25) C7(0.75,1.25) C8(1.25,1.25) C10(2.25,1.25) D1(-2.25,0.75) D3(-1.25,0.75) D8(1.25,0.75) D10(2.25,0.75) E1(-2.25,0.25) E3(-1.25,0.25) E8(1.25,0.25) E10(2.25,0.25) F1(-2.25,-0.25) F3(-1.25,-0.25) F8(1.25,-0.25) F10(2.25,-0.25) G1(-2.25,-0.75) G3(-1.25,-0.75) G8(1.25,-0.75) G10(2.25,-0.75) H1(-2.25,-1.25) H3(-1.25,-1.25) H4(-0.75,-1.25) H5(-0.25,-1.25) H6(0.25,-1.25) H7(0.75,-1.25) H8(1.25,-1.25) H10(2.25,-1.25) J1(-2.25,-1.75) J10(2.25,-1.75) K1(-2.25,-2.25) K2(-1.75,-2.25) K3(-1.25,-2.25) K4(-0.75,-2.25) K5(-0.25,-2.25) K6(0.25,-2.25) K7(0.75,-2.25) K8(1.25,-2.25) K9(1.75,-2.25) K10(2.25,-2.25)
Top Overlay:
  circle w0.25: c-3.65,2.25 r0.125
  region: -2.242,3 -3,2.242 -3,3
  lines w0.2: -3,2.242 -2.242,3 ; -3,-3 -3,3 3,3 3,-3 -3,-3
Mechanical 13:
  lines w0.1: -3,-3 -3,3 3,3 3,-3 -3,-3
Mechanical 15:
  lines w0.1: -0.5,0 0.5,0 ; 0,-0.5 0,0.5 ; -4,-4 -4,4 4,4 4,-4 -4,-4
3D body: height 1.35, standoff 0, extent -3,-3 3,3

## CPG132 [mm] "132-Ball Chip Scale Ball Grid Array 0.5 mm Pitch (CPG132) - Pb-Free"
height 1.1
pads (132):
  round 0.25 smd: A1(-3.25,3.25) A2(-2.75,3.25) A3(-2.25,3.25) A4(-1.75,3.25) A5(-1.25,3.25) A6(-0.75,3.25) A7(-0.25,3.25) A8(0.25,3.25) A9(0.75,3.25) A10(1.25,3.25) A11(1.75,3.25) A12(2.25,3.25) A13(2.75,3.25) A14(3.25,3.25) B1(-3.25,2.75) B2(-2.75,2.75) B3(-2.25,2.75) B4(-1.75,2.75) B5(-1.25,2.75) B6(-0.75,2.75) B7(-0.25,2.75) B8(0.25,2.75) B9(0.75,2.75) B10(1.25,2.75) B11(1.75,2.75) B12(2.25,2.75) B13(2.75,2.75) B14(3.25,2.75) C1(-3.25,2.25) C2(-2.75,2.25) C3(-2.25,2.25) C4(-1.75,2.25) C5(-1.25,2.25) C6(-0.75,2.25) C7(-0.25,2.25) C8(0.25,2.25) C9(0.75,2.25) C10(1.25,2.25) C11(1.75,2.25) C12(2.25,2.25) C13(2.75,2.25) C14(3.25,2.25) D1(-3.25,1.75) D2(-2.75,1.75) D3(-2.25,1.75) D12(2.25,1.75) D13(2.75,1.75) D14(3.25,1.75) E1(-3.25,1.25) E2(-2.75,1.25) E3(-2.25,1.25) E12(2.25,1.25) E13(2.75,1.25) E14(3.25,1.25) F1(-3.25,0.75) F2(-2.75,0.75) F3(-2.25,0.75) F12(2.25,0.75) F13(2.75,0.75) F14(3.25,0.75) G1(-3.25,0.25) G2(-2.75,0.25) G3(-2.25,0.25) G12(2.25,0.25) G13(2.75,0.25) G14(3.25,0.25) H1(-3.25,-0.25) H2(-2.75,-0.25) H3(-2.25,-0.25) H12(2.25,-0.25) H13(2.75,-0.25) H14(3.25,-0.25) J1(-3.25,-0.75) J2(-2.75,-0.75) J3(-2.25,-0.75) J12(2.25,-0.75) J13(2.75,-0.75) J14(3.25,-0.75) K1(-3.25,-1.25) K2(-2.75,-1.25) K3(-2.25,-1.25) K12(2.25,-1.25) K13(2.75,-1.25) K14(3.25,-1.25) L1(-3.25,-1.75) L2(-2.75,-1.75) L3(-2.25,-1.75) L12(2.25,-1.75) L13(2.75,-1.75) L14(3.25,-1.75) M1(-3.25,-2.25) M2(-2.75,-2.25) M3(-2.25,-2.25) M4(-1.75,-2.25) M5(-1.25,-2.25) M6(-0.75,-2.25) M7(-0.25,-2.25) M8(0.25,-2.25) M9(0.75,-2.25) M10(1.25,-2.25) M11(1.75,-2.25) M12(2.25,-2.25) M13(2.75,-2.25) M14(3.25,-2.25) N1(-3.25,-2.75) N2(-2.75,-2.75) N3(-2.25,-2.75) N4(-1.75,-2.75) N5(-1.25,-2.75) N6(-0.75,-2.75) N7(-0.25,-2.75) N8(0.25,-2.75) N9(0.75,-2.75) N10(1.25,-2.75) N11(1.75,-2.75) N12(2.25,-2.75) N13(2.75,-2.75) N14(3.25,-2.75) P1(-3.25,-3.25) P2(-2.75,-3.25) P3(-2.25,-3.25) P4(-1.75,-3.25) P5(-1.25,-3.25) P6(-0.75,-3.25) P7(-0.25,-3.25) P8(0.25,-3.25) P9(0.75,-3.25) P10(1.25,-3.25) P11(1.75,-3.25) P12(2.25,-3.25) P13(2.75,-3.25) P14(3.25,-3.25)
Top Overlay:
  circle w0.25: c-4.65,3.25 r0.125
  region: -3.242,4 -4,3.242 -4,4
  lines w0.2: -4,3.242 -3.242,4 ; -4,-4 -4,4 4,4 4,-4 -4,-4
Mechanical 13:
  lines w0.1: -4,-4 -4,4 4,4 4,-4 -4,-4
Mechanical 15:
  lines w0.1: -0.5,0 0.5,0 ; 0,-0.5 0,0.5 ; -5,-5 -5,5 5,5 5,-5 -5,-5
3D body: height 1.1, standoff 0, extent -4,-4 4,4

## CS48 [mm] "48-Ball Chip Scale Ball Grid Array (CS48)"
height 1.8
pads (48):
  round 0.45 smd: A1(-2.4,2.4) A2(-1.6,2.4) A3(-0.8,2.4) A4(0,2.4) A5(0.8,2.4) A6(1.6,2.4) A7(2.4,2.4) B1(-2.4,1.6) B2(-1.6,1.6) B3(-0.8,1.6) B4(0,1.6) B5(0.8,1.6) B6(1.6,1.6) B7(2.4,1.6) C1(-2.4,0.8) C2(-1.6,0.8) C3(-0.8,0.8) C4(0,0.8) C5(0.8,0.8) C6(1.6,0.8) C7(2.4,0.8) D1(-2.4,0) D2(-1.6,0) D3(-0.8,0) D4(0,0) D6(1.6,0) D7(2.4,0) E1(-2.4,-0.8) E2(-1.6,-0.8) E3(-0.8,-0.8) E4(0,-0.8) E5(0.8,-0.8) E6(1.6,-0.8) E7(2.4,-0.8) F1(-2.4,-1.6) F2(-1.6,-1.6) F3(-0.8,-1.6) F4(0,-1.6) F5(0.8,-1.6) F6(1.6,-1.6) F7(2.4,-1.6) G1(-2.4,-2.4) G2(-1.6,-2.4) G3(-0.8,-2.4) G4(0,-2.4) G5(0.8,-2.4) G6(1.6,-2.4) G7(2.4,-2.4)
Top Overlay:
  circle w0.25: c-4.15,2.4 r0.125
  region: -2.5,3.5 -3.5,2.5 -3.5,3.5
  lines w0.2: -3.5,2.5 -2.5,3.5 ; -3.5,-3.5 3.5,-3.5 3.5,3.5 -3.5,3.5 -3.5,-3.5
Mechanical 13:
  lines w0.1: -3.5,-3.5 3.5,-3.5 3.5,3.5 -3.5,3.5 -3.5,-3.5
Mechanical 15:
  lines w0.1: -0.5,0 0.5,0 ; 0,-0.5 0,0.5 ; -4.5,-4.5 4.5,-4.5 4.5,4.5 -4.5,4.5 -4.5,-4.5
3D body: height 1.8, standoff 0, extent -3.5,-3.5 3.5,3.5

## CS144 [mm] "144-Ball Chip Scale Ball Grid Array (CS144)"
height 1.2
pads (144):
  round 0.4 smd: A1(-4.8,4.8) A2(-4,4.8) A3(-3.2,4.8) A4(-2.4,4.8) A5(-1.6,4.8) A6(-0.8,4.8) A7(0,4.8) A8(0.8,4.8) A9(1.6,4.8) A10(2.4,4.8) A11(3.2,4.8) A12(4,4.8) A13(4.8,4.8) B1(-4.8,4) B2(-4,4) B3(-3.2,4) B4(-2.4,4) B5(-1.6,4) B6(-0.8,4) B7(0,4) B8(0.8,4) B9(1.6,4) B10(2.4,4) B11(3.2,4) B12(4,4) B13(4.8,4) C1(-4.8,3.2) C2(-4,3.2) C3(-3.2,3.2) C4(-2.4,3.2) C5(-1.6,3.2) C6(-0.8,3.2) C7(0,3.2) C8(0.8,3.2) C9(1.6,3.2) C10(2.4,3.2) C11(3.2,3.2) C12(4,3.2) C13(4.8,3.2) D1(-4.8,2.4) D2(-4,2.4) D3(-3.2,2.4) D4(-2.4,2.4) D5(-1.6,2.4) D6(-0.8,2.4) D7(0,2.4) D8(0.8,2.4) D9(1.6,2.4) D10(2.4,2.4) D11(3.2,2.4) D12(4,2.4) D13(4.8,2.4) E1(-4.8,1.6) E2(-4,1.6) E3(-3.2,1.6) E4(-2.4,1.6) E10(2.4,1.6) E11(3.2,1.6) E12(4,1.6) E13(4.8,1.6) F1(-4.8,0.8) F2(-4,0.8) F3(-3.2,0.8) F4(-2.4,0.8) F10(2.4,0.8) F11(3.2,0.8) F12(4,0.8) F13(4.8,0.8) G1(-4.8,0) G2(-4,0) G3(-3.2,0) G4(-2.4,0) G10(2.4,0) G11(3.2,0) G12(4,0) G13(4.8,0) H1(-4.8,-0.8) H2(-4,-0.8) H3(-3.2,-0.8) H4(-2.4,-0.8) H10(2.4,-0.8) H11(3.2,-0.8) H12(4,-0.8) H13(4.8,-0.8) J1(-4.8,-1.6) J2(-4,-1.6) J3(-3.2,-1.6) J4(-2.4,-1.6) J10(2.4,-1.6) J11(3.2,-1.6) J12(4,-1.6) J13(4.8,-1.6) K1(-4.8,-2.4) K2(-4,-2.4) K3(-3.2,-2.4) K4(-2.4,-2.4) K5(-1.6,-2.4) K6(-0.8,-2.4) K7(0,-2.4) K8(0.8,-2.4) K9(1.6,-2.4) K10(2.4,-2.4) K11(3.2,-2.4) K12(4,-2.4) K13(4.8,-2.4) L1(-4.8,-3.2) L2(-4,-3.2) L3(-3.2,-3.2) L4(-2.4,-3.2) L5(-1.6,-3.2) L6(-0.8,-3.2) L7(0,-3.2) L8(0.8,-3.2) L9(1.6,-3.2) L10(2.4,-3.2) L11(3.2,-3.2) L12(4,-3.2) L13(4.8,-3.2) M1(-4.8,-4) M2(-4,-4) M3(-3.2,-4) M4(-2.4,-4) M5(-1.6,-4) M6(-0.8,-4) M7(0,-4) M8(0.8,-4) M9(1.6,-4) M10(2.4,-4) M11(3.2,-4) M12(4,-4) M13(4.8,-4) N1(-4.8,-4.8) N2(-4,-4.8) N3(-3.2,-4.8) N4(-2.4,-4.8) N5(-1.6,-4.8) N6(-0.8,-4.8) N7(0,-4.8) N8(0.8,-4.8) N9(1.6,-4.8) N10(2.4,-4.8) N11(3.2,-4.8) N12(4,-4.8) N13(4.8,-4.8)
Top Overlay:
  circle w0.25: c-6.65,4.8 r0.125
  region: -5,6 -6,5 -6,6
  lines w0.2: -6,5 -5,6 ; -6,-6 6,-6 6,6 -6,6 -6,-6
Mechanical 13:
  lines w0.1: -6,-6 6,-6 6,6 -6,6 -6,-6
Mechanical 15:
  lines w0.1: -0.5,0 0.5,0 ; 0,-0.5 0,0.5 ; -7,-7 7,-7 7,7 -7,7 -7,-7
3D body: height 1.2, standoff 0, extent -6,-6 6,6

## CS280 [mm] "280-Ball Chip Scale Ball Grid Array (CS280)"
height 1.2
pads (280):
  round 0.4 smd: A1(-7.2,7.2) A2(-6.4,7.2) A3(-5.6,7.2) A4(-4.8,7.2) A5(-4,7.2) A6(-3.2,7.2) A7(-2.4,7.2) A8(-1.6,7.2) A9(-0.8,7.2) A10(0,7.2) A11(0.8,7.2) A12(1.6,7.2) A13(2.4,7.2) A14(3.2,7.2) A15(4,7.2) A16(4.8,7.2) A17(5.6,7.2) A18(6.4,7.2) A19(7.2,7.2) B1(-7.2,6.4) B2(-6.4,6.4) B3(-5.6,6.4) B4(-4.8,6.4) B5(-4,6.4) B6(-3.2,6.4) B7(-2.4,6.4) B8(-1.6,6.4) B9(-0.8,6.4) B10(0,6.4) B11(0.8,6.4) B12(1.6,6.4) B13(2.4,6.4) B14(3.2,6.4) B15(4,6.4) B16(4.8,6.4) B17(5.6,6.4) B18(6.4,6.4) B19(7.2,6.4) C1(-7.2,5.6) C2(-6.4,5.6) C3(-5.6,5.6) C4(-4.8,5.6) C5(-4,5.6) C6(-3.2,5.6) C7(-2.4,5.6) C8(-1.6,5.6) C9(-0.8,5.6) C10(0,5.6) C11(0.8,5.6) C12(1.6,5.6) C13(2.4,5.6) C14(3.2,5.6) C15(4,5.6) C16(4.8,5.6) C17(5.6,5.6) C18(6.4,5.6) C19(7.2,5.6) D1(-7.2,4.8) D2(-6.4,4.8) D3(-5.6,4.8) D4(-4.8,4.8) D5(-4,4.8) D6(-3.2,4.8) D7(-2.4,4.8) D8(-1.6,4.8) D9(-0.8,4.8) D10(0,4.8) D11(0.8,4.8) D12(1.6,4.8) D13(2.4,4.8) D14(3.2,4.8) D15(4,4.8) D16(4.8,4.8) D17(5.6,4.8) D18(6.4,4.8) D19(7.2,4.8) E1(-7.2,4) E2(-6.4,4) E3(-5.6,4) E4(-4.8,4) E5(-4,4) E6(-3.2,4) E7(-2.4,4) E8(-1.6,4) E9(-0.8,4) E10(0,4) E11(0.8,4) E12(1.6,4) E13(2.4,4) E14(3.2,4) E15(4,4) E16(4.8,4) E17(5.6,4) E18(6.4,4) E19(7.2,4) F1(-7.2,3.2) F2(-6.4,3.2) F3(-5.6,3.2) F4(-4.8,3.2) F5(-4,3.2) F15(4,3.2) F16(4.8,3.2) F17(5.6,3.2) F18(6.4,3.2) F19(7.2,3.2) G1(-7.2,2.4) G2(-6.4,2.4) G3(-5.6,2.4) G4(-4.8,2.4) G5(-4,2.4) G15(4,2.4) G16(4.8,2.4) G17(5.6,2.4) G18(6.4,2.4) G19(7.2,2.4) H1(-7.2,1.6) H2(-6.4,1.6) H3(-5.6,1.6) H4(-4.8,1.6) H5(-4,1.6) H15(4,1.6) H16(4.8,1.6) H17(5.6,1.6) H18(6.4,1.6) H19(7.2,1.6) J1(-7.2,0.8) J2(-6.4,0.8) J3(-5.6,0.8) J4(-4.8,0.8) J5(-4,0.8) J15(4,0.8) J16(4.8,0.8) J17(5.6,0.8) J18(6.4,0.8) J19(7.2,0.8) K1(-7.2,0) K2(-6.4,0) K3(-5.6,0) K4(-4.8,0) K5(-4,0) K15(4,0) K16(4.8,0) K17(5.6,0) K18(6.4,0) K19(7.2,0) L1(-7.2,-0.8) L2(-6.4,-0.8) L3(-5.6,-0.8) L4(-4.8,-0.8) L5(-4,-0.8) L15(4,-0.8) L16(4.8,-0.8) L17(5.6,-0.8) L18(6.4,-0.8) L19(7.2,-0.8) M1(-7.2,-1.6) M2(-6.4,-1.6) M3(-5.6,-1.6) M4(-4.8,-1.6) M5(-4,-1.6) M15(4,-1.6) M16(4.8,-1.6) M17(5.6,-1.6) M18(6.4,-1.6) M19(7.2,-1.6) N1(-7.2,-2.4) N2(-6.4,-2.4) N3(-5.6,-2.4) N4(-4.8,-2.4) N5(-4,-2.4) N15(4,-2.4) N16(4.8,-2.4) N17(5.6,-2.4) N18(6.4,-2.4) N19(7.2,-2.4) P1(-7.2,-3.2) P2(-6.4,-3.2) P3(-5.6,-3.2) P4(-4.8,-3.2) P5(-4,-3.2) P15(4,-3.2) P16(4.8,-3.2) P17(5.6,-3.2) P18(6.4,-3.2) P19(7.2,-3.2) R1(-7.2,-4) R2(-6.4,-4) R3(-5.6,-4) R4(-4.8,-4) R5(-4,-4) R6(-3.2,-4) R7(-2.4,-4) R8(-1.6,-4) R9(-0.8,-4) R10(0,-4) R11(0.8,-4) R12(1.6,-4) R13(2.4,-4) R14(3.2,-4) R15(4,-4) R16(4.8,-4) R17(5.6,-4) R18(6.4,-4) R19(7.2,-4) T1(-7.2,-4.8) T2(-6.4,-4.8) T3(-5.6,-4.8) T4(-4.8,-4.8) T5(-4,-4.8) T6(-3.2,-4.8) T7(-2.4,-4.8) T8(-1.6,-4.8) T9(-0.8,-4.8) T10(0,-4.8) T11(0.8,-4.8) T12(1.6,-4.8) T13(2.4,-4.8) T14(3.2,-4.8) T15(4,-4.8) T16(4.8,-4.8) T17(5.6,-4.8) T18(6.4,-4.8) T19(7.2,-4.8) U1(-7.2,-5.6) U2(-6.4,-5.6) U3(-5.6,-5.6) U4(-4.8,-5.6) U5(-4,-5.6) U6(-3.2,-5.6) U7(-2.4,-5.6) U8(-1.6,-5.6) U9(-0.8,-5.6) U10(0,-5.6) U11(0.8,-5.6) U12(1.6,-5.6) U13(2.4,-5.6) U14(3.2,-5.6) U15(4,-5.6) U16(4.8,-5.6) U17(5.6,-5.6) U18(6.4,-5.6) U19(7.2,-5.6) V1(-7.2,-6.4) V2(-6.4,-6.4) V3(-5.6,-6.4) V4(-4.8,-6.4) V5(-4,-6.4) V6(-3.2,-6.4) V7(-2.4,-6.4) V8(-1.6,-6.4) V9(-0.8,-6.4) V10(0,-6.4) V11(0.8,-6.4) V12(1.6,-6.4) V13(2.4,-6.4) V14(3.2,-6.4) V15(4,-6.4) V16(4.8,-6.4) V17(5.6,-6.4) V18(6.4,-6.4) V19(7.2,-6.4) W1(-7.2,-7.2) W2(-6.4,-7.2) W3(-5.6,-7.2) W4(-4.8,-7.2) W5(-4,-7.2) W6(-3.2,-7.2) W7(-2.4,-7.2) W8(-1.6,-7.2) W9(-0.8,-7.2) W10(0,-7.2) W11(0.8,-7.2) W12(1.6,-7.2) W13(2.4,-7.2) W14(3.2,-7.2) W15(4,-7.2) W16(4.8,-7.2) W17(5.6,-7.2) W18(6.4,-7.2) W19(7.2,-7.2)
Top Overlay:
  circle w0.25: c-8.65,7.2 r0.125
  region: -7.249,8 -8,7.249 -8,8
  lines w0.2: -8,7.249 -7.249,8 ; -8,-8 8,-8 8,8 -8,8 -8,-8
Mechanical 13:
  lines w0.1: -8,-8 8,-8 8,8 -8,8 -8,-8
Mechanical 15:
  lines w0.1: -0.5,0 0.5,0 ; 0,-0.5 0,0.5 ; -9,-9 9,-9 9,9 -9,9 -9,-9
3D body: height 1.2, standoff 0, extent -8,-8 8,8

## CSG48 [mm] "48-Ball Chip Scale Ball Grid Array (CSG48) - Pb-Free"
height 1.8
pads (48):
  round 0.45 smd: A1(-2.4,2.4) A2(-1.6,2.4) A3(-0.8,2.4) A4(0,2.4) A5(0.8,2.4) A6(1.6,2.4) A7(2.4,2.4) B1(-2.4,1.6) B2(-1.6,1.6) B3(-0.8,1.6) B4(0,1.6) B5(0.8,1.6) B6(1.6,1.6) B7(2.4,1.6) C1(-2.4,0.8) C2(-1.6,0.8) C3(-0.8,0.8) C4(0,0.8) C5(0.8,0.8) C6(1.6,0.8) C7(2.4,0.8) D1(-2.4,0) D2(-1.6,0) D3(-0.8,0) D4(0,0) D6(1.6,0) D7(2.4,0) E1(-2.4,-0.8) E2(-1.6,-0.8) E3(-0.8,-0.8) E4(0,-0.8) E5(0.8,-0.8) E6(1.6,-0.8) E7(2.4,-0.8) F1(-2.4,-1.6) F2(-1.6,-1.6) F3(-0.8,-1.6) F4(0,-1.6) F5(0.8,-1.6) F6(1.6,-1.6) F7(2.4,-1.6) G1(-2.4,-2.4) G2(-1.6,-2.4) G3(-0.8,-2.4) G4(0,-2.4) G5(0.8,-2.4) G6(1.6,-2.4) G7(2.4,-2.4)
Top Overlay:
  circle w0.25: c-4.15,2.4 r0.125
  region: -2.5,3.5 -3.5,2.5 -3.5,3.5
  lines w0.2: -3.5,2.5 -2.5,3.5 ; -3.5,-3.5 -3.5,3.5 3.5,3.5 3.5,-3.5 -3.5,-3.5
Mechanical 13:
  lines w0.1: -3.5,-3.5 -3.5,3.5 3.5,3.5 3.5,-3.5 -3.5,-3.5
Mechanical 15:
  lines w0.1: -0.5,0 0.5,0 ; 0,-0.5 0,0.5 ; -4.5,-4.5 -4.5,4.5 4.5,4.5 4.5,-4.5 -4.5,-4.5
3D body: height 1.8, standoff 0, extent -3.5,-3.5 3.5,3.5

## CSG144 [mm] "144-Ball Chip Scale Ball Grid Array (CSG144) - Pb-Free"
height 1.2
pads (144):
  round 0.4 smd: A1(-4.8,4.8) A2(-4,4.8) A3(-3.2,4.8) A4(-2.4,4.8) A5(-1.6,4.8) A6(-0.8,4.8) A7(0,4.8) A8(0.8,4.8) A9(1.6,4.8) A10(2.4,4.8) A11(3.2,4.8) A12(4,4.8) A13(4.8,4.8) B1(-4.8,4) B2(-4,4) B3(-3.2,4) B4(-2.4,4) B5(-1.6,4) B6(-0.8,4) B7(0,4) B8(0.8,4) B9(1.6,4) B10(2.4,4) B11(3.2,4) B12(4,4) B13(4.8,4) C1(-4.8,3.2) C2(-4,3.2) C3(-3.2,3.2) C4(-2.4,3.2) C5(-1.6,3.2) C6(-0.8,3.2) C7(0,3.2) C8(0.8,3.2) C9(1.6,3.2) C10(2.4,3.2) C11(3.2,3.2) C12(4,3.2) C13(4.8,3.2) D1(-4.8,2.4) D2(-4,2.4) D3(-3.2,2.4) D4(-2.4,2.4) D5(-1.6,2.4) D6(-0.8,2.4) D7(0,2.4) D8(0.8,2.4) D9(1.6,2.4) D10(2.4,2.4) D11(3.2,2.4) D12(4,2.4) D13(4.8,2.4) E1(-4.8,1.6) E2(-4,1.6) E3(-3.2,1.6) E4(-2.4,1.6) E10(2.4,1.6) E11(3.2,1.6) E12(4,1.6) E13(4.8,1.6) F1(-4.8,0.8) F2(-4,0.8) F3(-3.2,0.8) F4(-2.4,0.8) F10(2.4,0.8) F11(3.2,0.8) F12(4,0.8) F13(4.8,0.8) G1(-4.8,0) G2(-4,0) G3(-3.2,0) G4(-2.4,0) G10(2.4,0) G11(3.2,0) G12(4,0) G13(4.8,0) H1(-4.8,-0.8) H2(-4,-0.8) H3(-3.2,-0.8) H4(-2.4,-0.8) H10(2.4,-0.8) H11(3.2,-0.8) H12(4,-0.8) H13(4.8,-0.8) J1(-4.8,-1.6) J2(-4,-1.6) J3(-3.2,-1.6) J4(-2.4,-1.6) J10(2.4,-1.6) J11(3.2,-1.6) J12(4,-1.6) J13(4.8,-1.6) K1(-4.8,-2.4) K2(-4,-2.4) K3(-3.2,-2.4) K4(-2.4,-2.4) K5(-1.6,-2.4) K6(-0.8,-2.4) K7(0,-2.4) K8(0.8,-2.4) K9(1.6,-2.4) K10(2.4,-2.4) K11(3.2,-2.4) K12(4,-2.4) K13(4.8,-2.4) L1(-4.8,-3.2) L2(-4,-3.2) L3(-3.2,-3.2) L4(-2.4,-3.2) L5(-1.6,-3.2) L6(-0.8,-3.2) L7(0,-3.2) L8(0.8,-3.2) L9(1.6,-3.2) L10(2.4,-3.2) L11(3.2,-3.2) L12(4,-3.2) L13(4.8,-3.2) M1(-4.8,-4) M2(-4,-4) M3(-3.2,-4) M4(-2.4,-4) M5(-1.6,-4) M6(-0.8,-4) M7(0,-4) M8(0.8,-4) M9(1.6,-4) M10(2.4,-4) M11(3.2,-4) M12(4,-4) M13(4.8,-4) N1(-4.8,-4.8) N2(-4,-4.8) N3(-3.2,-4.8) N4(-2.4,-4.8) N5(-1.6,-4.8) N6(-0.8,-4.8) N7(0,-4.8) N8(0.8,-4.8) N9(1.6,-4.8) N10(2.4,-4.8) N11(3.2,-4.8) N12(4,-4.8) N13(4.8,-4.8)
Top Overlay:
  circle w0.25: c-6.65,4.8 r0.125
  region: -5,6 -6,5 -6,6
  lines w0.2: -6,5 -5,6 ; -6,-6 6,-6 6,6 -6,6 -6,-6
Mechanical 13:
  lines w0.1: -6,-6 6,-6 6,6 -6,6 -6,-6
Mechanical 15:
  lines w0.1: -0.5,0 0.5,0 ; 0,-0.5 0,0.5 ; -7,-7 7,-7 7,7 -7,7 -7,-7
3D body: height 1.2, standoff 0, extent -6,-6 6,6

## CSG280 [mm] "280-Ball Chip Scale Ball Grid Array (CSG280) - Pb-Free"
height 1.2
pads (280):
  round 0.4 smd: A1(-7.2,7.2) A2(-6.4,7.2) A3(-5.6,7.2) A4(-4.8,7.2) A5(-4,7.2) A6(-3.2,7.2) A7(-2.4,7.2) A8(-1.6,7.2) A9(-0.8,7.2) A10(0,7.2) A11(0.8,7.2) A12(1.6,7.2) A13(2.4,7.2) A14(3.2,7.2) A15(4,7.2) A16(4.8,7.2) A17(5.6,7.2) A18(6.4,7.2) A19(7.2,7.2) B1(-7.2,6.4) B2(-6.4,6.4) B3(-5.6,6.4) B4(-4.8,6.4) B5(-4,6.4) B6(-3.2,6.4) B7(-2.4,6.4) B8(-1.6,6.4) B9(-0.8,6.4) B10(0,6.4) B11(0.8,6.4) B12(1.6,6.4) B13(2.4,6.4) B14(3.2,6.4) B15(4,6.4) B16(4.8,6.4) B17(5.6,6.4) B18(6.4,6.4) B19(7.2,6.4) C1(-7.2,5.6) C2(-6.4,5.6) C3(-5.6,5.6) C4(-4.8,5.6) C5(-4,5.6) C6(-3.2,5.6) C7(-2.4,5.6) C8(-1.6,5.6) C9(-0.8,5.6) C10(0,5.6) C11(0.8,5.6) C12(1.6,5.6) C13(2.4,5.6) C14(3.2,5.6) C15(4,5.6) C16(4.8,5.6) C17(5.6,5.6) C18(6.4,5.6) C19(7.2,5.6) D1(-7.2,4.8) D2(-6.4,4.8) D3(-5.6,4.8) D4(-4.8,4.8) D5(-4,4.8) D6(-3.2,4.8) D7(-2.4,4.8) D8(-1.6,4.8) D9(-0.8,4.8) D10(0,4.8) D11(0.8,4.8) D12(1.6,4.8) D13(2.4,4.8) D14(3.2,4.8) D15(4,4.8) D16(4.8,4.8) D17(5.6,4.8) D18(6.4,4.8) D19(7.2,4.8) E1(-7.2,4) E2(-6.4,4) E3(-5.6,4) E4(-4.8,4) E5(-4,4) E6(-3.2,4) E7(-2.4,4) E8(-1.6,4) E9(-0.8,4) E10(0,4) E11(0.8,4) E12(1.6,4) E13(2.4,4) E14(3.2,4) E15(4,4) E16(4.8,4) E17(5.6,4) E18(6.4,4) E19(7.2,4) F1(-7.2,3.2) F2(-6.4,3.2) F3(-5.6,3.2) F4(-4.8,3.2) F5(-4,3.2) F15(4,3.2) F16(4.8,3.2) F17(5.6,3.2) F18(6.4,3.2) F19(7.2,3.2) G1(-7.2,2.4) G2(-6.4,2.4) G3(-5.6,2.4) G4(-4.8,2.4) G5(-4,2.4) G15(4,2.4) G16(4.8,2.4) G17(5.6,2.4) G18(6.4,2.4) G19(7.2,2.4) H1(-7.2,1.6) H2(-6.4,1.6) H3(-5.6,1.6) H4(-4.8,1.6) H5(-4,1.6) H15(4,1.6) H16(4.8,1.6) H17(5.6,1.6) H18(6.4,1.6) H19(7.2,1.6) J1(-7.2,0.8) J2(-6.4,0.8) J3(-5.6,0.8) J4(-4.8,0.8) J5(-4,0.8) J15(4,0.8) J16(4.8,0.8) J17(5.6,0.8) J18(6.4,0.8) J19(7.2,0.8) K1(-7.2,0) K2(-6.4,0) K3(-5.6,0) K4(-4.8,0) K5(-4,0) K15(4,0) K16(4.8,0) K17(5.6,0) K18(6.4,0) K19(7.2,0) L1(-7.2,-0.8) L2(-6.4,-0.8) L3(-5.6,-0.8) L4(-4.8,-0.8) L5(-4,-0.8) L15(4,-0.8) L16(4.8,-0.8) L17(5.6,-0.8) L18(6.4,-0.8) L19(7.2,-0.8) M1(-7.2,-1.6) M2(-6.4,-1.6) M3(-5.6,-1.6) M4(-4.8,-1.6) M5(-4,-1.6) M15(4,-1.6) M16(4.8,-1.6) M17(5.6,-1.6) M18(6.4,-1.6) M19(7.2,-1.6) N1(-7.2,-2.4) N2(-6.4,-2.4) N3(-5.6,-2.4) N4(-4.8,-2.4) N5(-4,-2.4) N15(4,-2.4) N16(4.8,-2.4) N17(5.6,-2.4) N18(6.4,-2.4) N19(7.2,-2.4) P1(-7.2,-3.2) P2(-6.4,-3.2) P3(-5.6,-3.2) P4(-4.8,-3.2) P5(-4,-3.2) P15(4,-3.2) P16(4.8,-3.2) P17(5.6,-3.2) P18(6.4,-3.2) P19(7.2,-3.2) R1(-7.2,-4) R2(-6.4,-4) R3(-5.6,-4) R4(-4.8,-4) R5(-4,-4) R6(-3.2,-4) R7(-2.4,-4) R8(-1.6,-4) R9(-0.8,-4) R10(0,-4) R11(0.8,-4) R12(1.6,-4) R13(2.4,-4) R14(3.2,-4) R15(4,-4) R16(4.8,-4) R17(5.6,-4) R18(6.4,-4) R19(7.2,-4) T1(-7.2,-4.8) T2(-6.4,-4.8) T3(-5.6,-4.8) T4(-4.8,-4.8) T5(-4,-4.8) T6(-3.2,-4.8) T7(-2.4,-4.8) T8(-1.6,-4.8) T9(-0.8,-4.8) T10(0,-4.8) T11(0.8,-4.8) T12(1.6,-4.8) T13(2.4,-4.8) T14(3.2,-4.8) T15(4,-4.8) T16(4.8,-4.8) T17(5.6,-4.8) T18(6.4,-4.8) T19(7.2,-4.8) U1(-7.2,-5.6) U2(-6.4,-5.6) U3(-5.6,-5.6) U4(-4.8,-5.6) U5(-4,-5.6) U6(-3.2,-5.6) U7(-2.4,-5.6) U8(-1.6,-5.6) U9(-0.8,-5.6) U10(0,-5.6) U11(0.8,-5.6) U12(1.6,-5.6) U13(2.4,-5.6) U14(3.2,-5.6) U15(4,-5.6) U16(4.8,-5.6) U17(5.6,-5.6) U18(6.4,-5.6) U19(7.2,-5.6) V1(-7.2,-6.4) V2(-6.4,-6.4) V3(-5.6,-6.4) V4(-4.8,-6.4) V5(-4,-6.4) V6(-3.2,-6.4) V7(-2.4,-6.4) V8(-1.6,-6.4) V9(-0.8,-6.4) V10(0,-6.4) V11(0.8,-6.4) V12(1.6,-6.4) V13(2.4,-6.4) V14(3.2,-6.4) V15(4,-6.4) V16(4.8,-6.4) V17(5.6,-6.4) V18(6.4,-6.4) V19(7.2,-6.4) W1(-7.2,-7.2) W2(-6.4,-7.2) W3(-5.6,-7.2) W4(-4.8,-7.2) W5(-4,-7.2) W6(-3.2,-7.2) W7(-2.4,-7.2) W8(-1.6,-7.2) W9(-0.8,-7.2) W10(0,-7.2) W11(0.8,-7.2) W12(1.6,-7.2) W13(2.4,-7.2) W14(3.2,-7.2) W15(4,-7.2) W16(4.8,-7.2) W17(5.6,-7.2) W18(6.4,-7.2) W19(7.2,-7.2)
Top Overlay:
  circle w0.25: c-8.65,7.2 r0.125
  region: -7.249,8 -8,7.249 -8,8
  lines w0.2: -8,7.249 -7.249,8 ; -8,-8 8,-8 8,8 -8,8 -8,-8
Mechanical 13:
  lines w0.1: -8,-8 8,-8 8,8 -8,8 -8,-8
Mechanical 15:
  lines w0.1: -0.5,0 0.5,0 ; 0,-0.5 0,0.5 ; -9,-9 9,-9 9,9 -9,9 -9,-9
3D body: height 1.2, standoff 0, extent -8,-8 8,8

## DD8 [mm] "8-Pin Ceramic DIP (DD8)"
height 5.08
pads (8):
  rect 1.5x1.5 hole 0.9: 1(-3.81,-3.81)
  round 1.5 hole 0.9: 2(-1.27,-3.81) 3(1.27,-3.81) 4(3.81,-3.81) 5(3.81,3.81) 6(1.27,3.81) 7(-1.27,3.81) 8(-3.81,3.81)
Top Overlay:
  lines w0.2: -5.5,-2.65 -5.5,-0.635 ccw(c-5.5,0) -5.5,0.635 -5.5,2.65 5.5,2.65 5.5,-2.65 -5.5,-2.65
